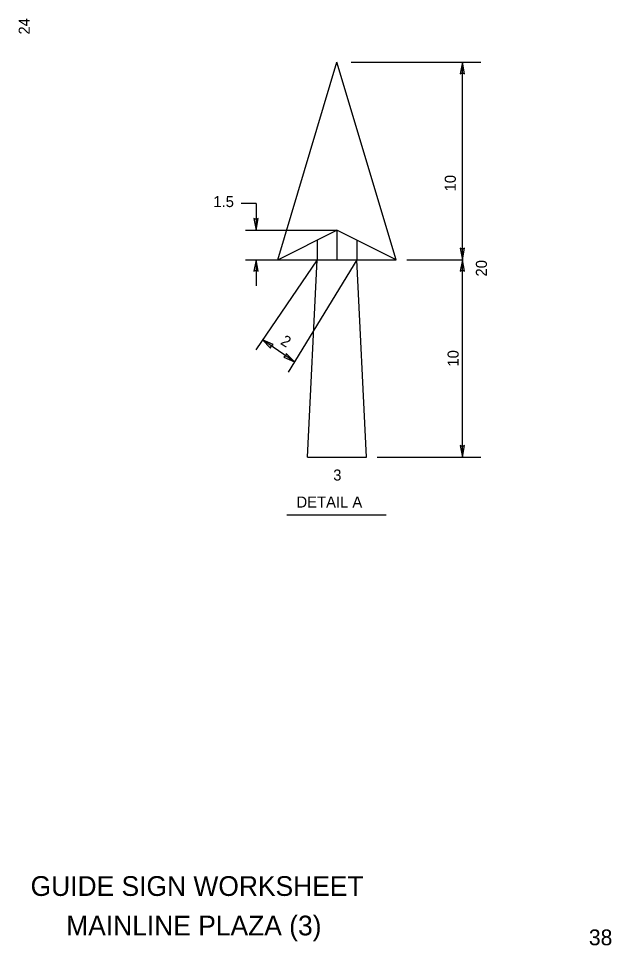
# Model space of a CAD drawing. Extents: x 319706 to 320019, y 1621790 to 1621976.
# Drawn here: x 319943.9 to 320019, y 1621795.1 to 1621912.5 of the extents above; entities that cross this region are included whole.
import ezdxf

# ---------------------------------------------------------------- set-up
doc = ezdxf.new("R2010")
doc.units = 0
for name, color, linetype in [('10', 7, 'Continuous'), ('38', 7, 'Continuous'), ('48', 7, 'Continuous'), ('52', 7, 'Continuous'), ('TextMisc', 7, 'Continuous'), ('TextShtNo', 7, 'Continuous')]:
    doc.layers.add(name, color=color, linetype=linetype)

msp = doc.modelspace()

# ---------------------------------------------------------------- linework, layer by layer
at = {"layer": '10'}
for p, q in [((319976.75, 1621881.96), (319984.25, 1621906.96)), ((319991.75, 1621881.96), (319984.25, 1621906.96)), ((319976.75, 1621881.96), (319984.25, 1621885.71)), ((319991.75, 1621881.96), (319984.25, 1621885.71)), ((319981.75, 1621884.46), (319981.75, 1621881.96)), ((319986.75, 1621884.46), (319986.75, 1621881.96)), ((319980.5, 1621856.96), (319981.75, 1621881.96)), ((319988, 1621856.96), (319986.75, 1621881.96)), ((319980.5, 1621856.96), (319988, 1621856.96))]:
    msp.add_line(p, q, dxfattribs=at)
at = {"layer": '38'}
msp.add_line((319977.91, 1621849.63), (319990.49, 1621849.63), dxfattribs=at)
at = {"layer": '48'}
for p, q in [((319986.06, 1621906.96), (320002.49, 1621906.96)), ((320000.14, 1621881.96), (320000.14, 1621906.96)), ((319974, 1621889.09), (319972.11, 1621889.09)), ((319974, 1621889.09), (319974, 1621885.71)), ((319972.68, 1621885.71), (319984.25, 1621885.71)), ((319984.25, 1621885.71), (319984.25, 1621881.96)), ((319972.68, 1621881.96), (319991.75, 1621881.96)), ((319981.75, 1621881.96), (319973.96, 1621870.55)), ((319974, 1621881.96), (319974, 1621878.66)), ((319986.75, 1621881.96), (319978.09, 1621867.73)), ((319993.1, 1621881.96), (320000.14, 1621881.96)), ((320000.14, 1621856.96), (320000.14, 1621881.96)), ((319978.88, 1621869.03), (319974.81, 1621871.8)), ((319989.34, 1621856.96), (320002.49, 1621856.96))]:
    msp.add_line(p, q, dxfattribs=at)
at = {"layer": '52'}
for p, q in [((320000.14, 1621906.96), (319999.86, 1621905.51)), ((320000.41, 1621905.51), (320000.14, 1621906.96)), ((319999.86, 1621905.51), (320000.14, 1621905.62)), ((320000.14, 1621905.62), (320000.41, 1621905.51)), ((319974, 1621887.05), (319973.73, 1621887.16)), ((319973.73, 1621887.16), (319974, 1621885.71)), ((319974, 1621885.71), (319974.28, 1621887.16)), ((319974.28, 1621887.16), (319974, 1621887.05)), ((320000.14, 1621883.3), (319999.87, 1621883.41)), ((319999.87, 1621883.41), (320000.14, 1621881.96)), ((320000.14, 1621881.96), (320000.42, 1621883.41)), ((320000.42, 1621883.41), (320000.14, 1621883.3)), ((319974, 1621881.96), (319973.72, 1621880.51)), ((319974.27, 1621880.51), (319974, 1621881.96)), ((320000.14, 1621881.96), (319999.86, 1621880.51)), ((320000.41, 1621880.51), (320000.14, 1621881.96)), ((319973.72, 1621880.51), (319974, 1621880.62)), ((319974, 1621880.62), (319974.27, 1621880.51)), ((319999.86, 1621880.51), (320000.14, 1621880.62)), ((320000.14, 1621880.62), (320000.41, 1621880.51)), ((319974.81, 1621871.8), (319975.85, 1621870.75)), ((319976.16, 1621871.2), (319974.81, 1621871.8)), ((319975.85, 1621870.75), (319975.92, 1621871.04)), ((319975.92, 1621871.04), (319976.16, 1621871.2)), ((319977.77, 1621869.78), (319977.53, 1621869.62)), ((319977.53, 1621869.62), (319978.88, 1621869.02)), ((319977.84, 1621870.07), (319977.77, 1621869.78)), ((319978.88, 1621869.02), (319977.84, 1621870.07)), ((320000.14, 1621858.3), (319999.87, 1621858.41)), ((319999.87, 1621858.41), (320000.14, 1621856.96)), ((320000.14, 1621856.96), (320000.42, 1621858.41)), ((320000.42, 1621858.41), (320000.14, 1621858.3))]:
    msp.add_line(p, q, dxfattribs=at)

# ---------------------------------------------------------------- texts
at = {"layer": '38'}
for s, rotation, p in [('10', 90, (319999.3, 1621890.61)), ('20', 90, (320003.24, 1621879.83)), ('2', 328.646, (319977, 1621871.32)), ('10', 90, (319999.66, 1621868.42))]:
    msp.add_text(s, height=1.4, rotation=rotation, dxfattribs=at).set_placement(p)
for s, p in [('1.5', (319968.6, 1621888.62)), ('3', (319983.78, 1621853.99)), ('DETAIL A', (319979.13, 1621850.57))]:
    msp.add_text(s, height=1.4, dxfattribs=at).set_placement(p)
at = {"layer": '48'}
msp.add_text('24', height=1.4, rotation=90, dxfattribs=at).set_placement((319945.35, 1621910.47))
at = {"layer": 'TextMisc'}
for s, p in [('  GUIDE SIGN WORKSHEET  ', (319943.6, 1621801.39)), ('   MAINLINE PLAZA (3)   ', (319947.18, 1621796.39))]:
    msp.add_text(s, height=2.5, rotation=360, dxfattribs=at).set_placement(p)
at = {"layer": 'TextShtNo'}
msp.add_text('38', height=2, rotation=360, dxfattribs=at).set_placement((320016.15, 1621795.14))

doc.saveas('drawing.dxf')
